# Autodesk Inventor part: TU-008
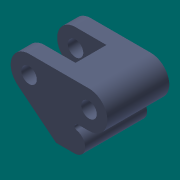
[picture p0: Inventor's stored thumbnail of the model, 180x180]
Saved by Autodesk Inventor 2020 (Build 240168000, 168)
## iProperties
Created: 2002-07
Part Number: TU-008
Document SubType Name: Modeling
Designer: PN
Density: 1 g/cm^3
Description: Hinge
Mass: 25.6282 g
Surface Area: 85.6046 cm^2
Volume: 25.6282 cm^3
Material: Generic
Appearance: Rubber (Blue)
Control State: 0
Master: False
Checked Out: False
Shininess: 64.0
Angle Display Precision: 2
Document Length Units: 11269
Document Angle Units: 11279
Document Time Units: 11290
Document Mass Units: 11286
Document Length Units Precision: 3
Document Angle Units Precision: 2
LENGTH: 1.000 in
Density: 0.0
Volumn: 0.0
Area: 0.0
PropertySet Name: Model Information
Author: PN
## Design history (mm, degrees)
sketch "Sketch1"
  geometry: L1 (31, 0)-(0, 0); L2 (14, -32.84)-(-5.582, -17.187); L3 (23.513, -32.84)-(14, -32.84); L4 (31, -19)-(25, -19); C1 r 4 at (0, -9.5); C2 r 4 at (31, -9.5); A1 r 9.5 centre (0, -9.5) between (0, 0) and (-5.582, -17.187); A2 r 5.5 centre (23.513, -27.34) between (23.513, -32.84) and (24.681, -21.966); A3 r 1.5 centre (25, -20.5) between (25, -19) and (24.681, -21.966); A4 r 9.5 centre (31, -9.5) between (31, -19) and (31, 0); 1 further point
  constraints: 8 end point, 8 point on circle, 7 tangent, 6 centre point, 2 coincident with centre, 2 parallel, 1 coincident, 1 equal radius, 1 horizontal
  dimensions: "d0" = 9.5 radius of A1; "d1" = 8 diameter of C1; "d2" = 31 distance of A4.centre A1.centre; "d3" = 1.5 radius of A3; "d4" = 5.5 radius of A2; "d6" = 9.51297 distance of L3.start L2.start; "d7" = 38.6376 deg angle of L3 L2; "d9" = 32.84023 distance between parallel lines of L3 L1; "d10" = 16.91036 distance from line of point (0, 0) L2
extrude "Extrusion1" new body sketch "Sketch1" stored distance "d11" = 32; taper "d12" = 0 deg
sketch "Sketch2"
  geometry: L1 (0, -32)-(0, 0) reference; L2 (-23.5, -32)-(-23.5, 0) reference; L3 (-23.5, -24)-(2, -24); L4 (2, -24)-(2, -8); L5 (2, -8)-(-23.5, -8); L6 (-23.5, -8)-(-23.5, -24); 1 further point
  constraints: 8 end point, 2 midpoint, 2 parallel, 1 horizontal, 1 perpendicular
  dimensions: "d13" = 2 distance between parallel lines of L4 L1; "d14" = 16 distance of L5.end L3.start
extrude "Extrusion2" cut sketch "Sketch2" extent not by distance; stored distance "d15" = 32; taper "d16" = 0 deg
hole "Hole1" diameter "d19" = 8; stored, may be unused: countersink angle "d23" = 90 deg, drill point angle "d25" = 118 deg; dims "d17" = 10, "d18" = 10, "d20" = 6, "d21" = 4, "d22" = 2, "d24" = 8
hole "Hole2" diameter "d28" = 8; stored, may be unused: countersink angle "d32" = 90 deg, drill point angle "d34" = 118 deg; dims "d26" = 10, "d27" = 10, "d29" = 6, "d30" = 4, "d31" = 2, "d33" = 8
body "Solid1"
other parameters: "LENGTH" = 25.4 [user parameter]
